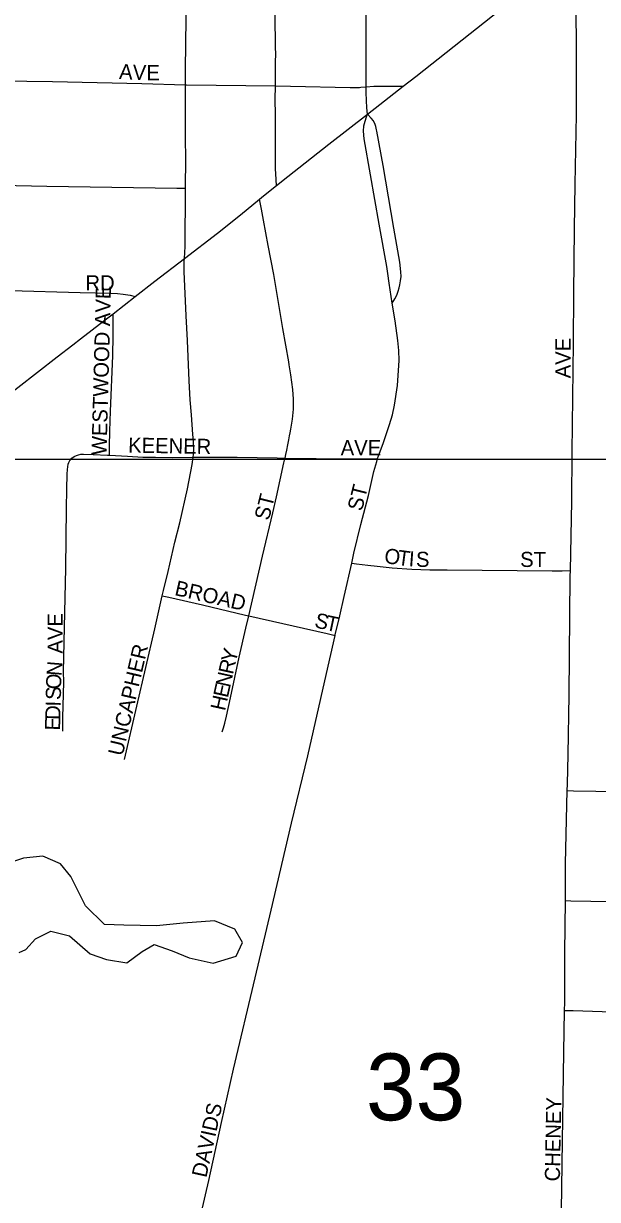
# Model space of a CAD drawing. Extents: x -97 to 34, y -21 to 22.
# Drawn here: x 4.741 to 5.1, y 18.009 to 18.745 of the extents above; entities that cross this region are included whole.
import ezdxf

# ---------------------------------------------------------------- set-up
doc = ezdxf.new("R2010")
doc.units = 0
for name, color, linetype in [('GM_X_City_Street', 7, 'Continuous'), ('GM_X_City_Street_Text', 7, 'Continuous'), ('GM_X_Minor_Lake', 7, 'Continuous'), ('GM_X_Section', 7, 'Continuous'), ('GM_X_Section_Text', 7, 'Continuous'), ('GM_X_State_Route', 7, 'Continuous')]:
    doc.layers.add(name, color=color, linetype=linetype)

msp = doc.modelspace()

# ---------------------------------------------------------------- linework, layer by layer
at = {"layer": 'GM_X_City_Street'}
for points in [[(4.89836, 18.70629), (4.89836, 18.70706), (4.89852, 18.72116), (4.89857, 18.72632), (4.89847, 18.73034), (4.89845, 18.73444), (4.89836, 18.73853), (4.89826, 18.74257), (4.89827, 18.74808), (4.89827, 18.75293), (4.89828, 18.7598), (4.89828, 18.7688), (4.89835, 18.77788), (4.89843, 18.78422), (4.89837, 18.79037), (4.89837, 18.79585)], [(4.95537, 18.70568), (4.95529, 18.71536), (4.95521, 18.72156), (4.95534, 18.734), (4.9552, 18.74025), (4.95529, 18.75266), (4.95567, 18.76511), (4.95578, 18.77134), (4.95571, 18.77508), (4.95562, 18.77982), (4.95561, 18.78606), (4.95563, 18.79544)], [(5.08331, 18.40259), (5.08422, 18.44581), (5.08438, 18.4769), (5.08522, 18.54525), (5.08539, 18.57633), (5.08594, 18.61672), (5.08627, 18.6447), (5.08676, 18.66643), (5.08703, 18.68815), (5.08708, 18.72231), (5.08692, 18.76271), (5.08725, 18.77201), (5.08742, 18.77817), (5.08728, 18.7812), (5.08681, 18.79085)], [(4.842, 18.70708), (4.84198, 18.70754), (4.84194, 18.71215), (4.84199, 18.71682), (4.84258, 18.76443)], [(4.72642, 18.70957), (4.75863, 18.70905), (4.81464, 18.70788), (4.842, 18.70708)], [(4.84203, 18.64224), (4.84223, 18.66089), (4.84208, 18.67334), (4.842, 18.70708)], [(4.842, 18.70708), (4.84257, 18.70706), (4.89836, 18.70629)], [(4.89905, 18.64383), (4.89862, 18.65117), (4.89845, 18.65426), (4.89845, 18.66671), (4.89841, 18.67749), (4.89837, 18.68845), (4.89828, 18.69774), (4.89836, 18.70629)], [(4.89836, 18.70629), (4.90793, 18.70612), (4.94533, 18.70539), (4.94688, 18.70539), (4.94925, 18.70539), (4.95103, 18.70542), (4.95201, 18.70548), (4.95537, 18.70568)], [(4.95621, 18.68865), (4.95576, 18.69255), (4.95557, 18.69714), (4.95534, 18.70217), (4.95537, 18.70568)], [(4.95537, 18.70568), (4.96016, 18.70607), (4.96202, 18.70614), (4.96445, 18.70624), (4.96758, 18.70618), (4.97539, 18.70612), (4.97849, 18.7061)], [(4.97166, 18.57029), (4.96972, 18.58266), (4.96881, 18.58871), (4.96819, 18.59316), (4.96336, 18.61965), (4.95791, 18.65057), (4.95399, 18.67322), (4.95359, 18.67796), (4.9539, 18.68126), (4.95457, 18.6843), (4.9556, 18.68704), (4.95621, 18.68865)], [(4.97166, 18.57029), (4.97324, 18.57287), (4.97446, 18.57526), (4.97527, 18.57763), (4.97597, 18.57974), (4.97641, 18.58168), (4.9769, 18.58409), (4.97729, 18.58682), (4.97711, 18.58992), (4.97642, 18.59591), (4.97255, 18.61713), (4.96589, 18.65641), (4.96202, 18.67787), (4.96186, 18.67878), (4.96159, 18.67991), (4.96137, 18.68083), (4.96092, 18.68214), (4.95985, 18.68438), (4.95843, 18.68611), (4.95621, 18.68865)], [(4.72621, 18.64411), (4.75512, 18.64341), (4.83665, 18.6423), (4.84203, 18.64224)], [(4.84136, 18.59824), (4.84183, 18.60569), (4.84177, 18.60786), (4.84185, 18.61109), (4.84185, 18.61727), (4.842, 18.62985), (4.84197, 18.63603), (4.84203, 18.64224)], [(4.90446, 18.47314), (4.90493, 18.4754), (4.90552, 18.47811), (4.90624, 18.4814), (4.90681, 18.48454), (4.90729, 18.4871), (4.90771, 18.489), (4.90812, 18.49132), (4.90917, 18.49747), (4.90972, 18.50369), (4.90978, 18.50994), (4.90935, 18.51613), (4.90809, 18.52531), (4.9071, 18.53148), (4.90678, 18.53342), (4.90307, 18.55439), (4.89736, 18.5881), (4.89391, 18.60642), (4.89094, 18.62213), (4.88963, 18.62901), (4.88843, 18.63538)], [(4.84679, 18.47368), (4.84701, 18.47534), (4.8472, 18.47887), (4.84711, 18.48168), (4.84702, 18.48384), (4.84657, 18.48789), (4.84571, 18.50022), (4.84492, 18.50959), (4.8444, 18.52149), (4.84338, 18.5468), (4.84255, 18.56233), (4.84116, 18.58999), (4.84125, 18.59644), (4.84136, 18.59824)], [(4.72613, 18.57818), (4.7324, 18.57804), (4.77596, 18.57685), (4.79494, 18.57641), (4.79938, 18.57618), (4.80302, 18.57589), (4.80732, 18.57524), (4.81057, 18.57446)], [(4.96249, 18.4728), (4.9636, 18.47614), (4.96587, 18.48233), (4.97002, 18.4941), (4.97171, 18.50013), (4.97301, 18.50625), (4.97487, 18.5186), (4.97539, 18.52483), (4.97588, 18.5342), (4.97572, 18.54047), (4.97516, 18.54671), (4.97355, 18.55906), (4.97166, 18.57029)], [(4.79443, 18.47496), (4.7945, 18.48055), (4.79463, 18.48999), (4.79508, 18.50261), (4.79645, 18.53726), (4.7966, 18.54983), (4.79663, 18.5561), (4.79666, 18.56358)], [(4.77088, 18.47309), (4.77235, 18.47409), (4.77366, 18.47478), (4.77505, 18.47524), (4.77644, 18.47548), (4.77813, 18.47555), (4.78407, 18.47545), (4.79325, 18.47502), (4.79443, 18.47496)], [(4.79443, 18.47496), (4.80574, 18.4744), (4.81538, 18.47379), (4.82316, 18.47364), (4.83402, 18.47343), (4.84679, 18.47368)], [(4.82749, 18.38689), (4.82822, 18.39023), (4.8311, 18.40208), (4.83545, 18.42039), (4.83842, 18.43258), (4.84325, 18.45379), (4.84619, 18.46908), (4.84679, 18.47368)], [(4.84679, 18.47368), (4.8496, 18.47373), (4.8745, 18.47361), (4.8995, 18.47321), (4.90446, 18.47314)], [(4.76507, 18.30198), (4.76518, 18.31062), (4.76549, 18.32511), (4.76569, 18.33289), (4.76566, 18.33909), (4.76645, 18.37628), (4.76695, 18.40419), (4.7674, 18.44142), (4.76758, 18.45365), (4.76779, 18.46314), (4.76804, 18.46592), (4.76855, 18.46926), (4.76888, 18.47038), (4.76958, 18.47162), (4.77088, 18.47309)], [(4.8817, 18.37433), (4.89035, 18.41161), (4.89676, 18.43888), (4.89903, 18.44892), (4.90368, 18.47023), (4.90433, 18.47264), (4.90446, 18.47314)], [(4.90446, 18.47314), (4.94329, 18.47256), (4.95584, 18.47272), (4.96249, 18.4728)], [(4.94624, 18.40725), (4.94764, 18.41349), (4.95202, 18.43157), (4.95666, 18.44964), (4.96013, 18.46473), (4.9619, 18.47104), (4.96249, 18.4728)], [(4.9358, 18.36197), (4.93587, 18.36227), (4.93885, 18.37423), (4.94157, 18.38631), (4.94624, 18.40725)], [(4.94624, 18.40725), (4.94925, 18.40689), (4.95629, 18.40604), (4.96216, 18.40534), (4.97151, 18.4044), (4.98402, 18.40352), (4.99519, 18.40314), (5.00599, 18.40308), (5.07192, 18.40241), (5.0782, 18.4025), (5.08331, 18.40259)], [(5.08138, 18.26474), (5.08147, 18.26872), (5.08182, 18.28735), (5.08244, 18.32463), (5.08324, 18.39922), (5.08331, 18.40259)], [(4.80378, 18.28433), (4.81153, 18.31764), (4.82288, 18.36607), (4.82749, 18.38689)], [(4.82749, 18.38689), (4.8317, 18.38593), (4.85272, 18.3811), (4.87973, 18.37478), (4.8817, 18.37433)], [(4.86503, 18.30155), (4.86588, 18.30417), (4.86668, 18.3071), (4.86767, 18.3113), (4.87031, 18.32279), (4.8756, 18.34832), (4.87985, 18.36646), (4.8817, 18.37433)], [(4.8817, 18.37433), (4.93082, 18.3631), (4.9358, 18.36197)], [(4.84651, 17.97642), (4.85676, 18.02036), (4.86457, 18.05681), (4.87208, 18.09012), (4.88581, 18.14752), (4.89567, 18.18987), (4.90857, 18.24427), (4.91877, 18.28654), (4.93052, 18.33804), (4.9358, 18.36197)], [(5.08014, 18.19589), (5.08031, 18.219), (5.08138, 18.26474)], [(5.08138, 18.26474), (5.08526, 18.26468), (5.11323, 18.26429), (5.15055, 18.26441), (5.18164, 18.26398), (5.21896, 18.26363), (5.26248, 18.26263), (5.29669, 18.26226), (5.30795, 18.26219), (5.31192, 18.26216)], [(5.0797, 18.12705), (5.07979, 18.13199), (5.07989, 18.16307), (5.08014, 18.19589)], [(5.08014, 18.19589), (5.08367, 18.19579), (5.09613, 18.19548), (5.13016, 18.19507), (5.15536, 18.19473), (5.17721, 18.19458), (5.20843, 18.19448), (5.22716, 18.19443), (5.25211, 18.19399), (5.27146, 18.19375), (5.27676, 18.19362), (5.28022, 18.19353)], [(5.07773, 17.97367), (5.0777, 17.97771), (5.07761, 17.98707), (5.07829, 18.04501), (5.07921, 18.10094), (5.0797, 18.12705)], [(5.0797, 18.12705), (5.08502, 18.12687), (5.10318, 18.12627), (5.12505, 18.12611), (5.14974, 18.12618), (5.1837, 18.12578), (5.22383, 18.12537), (5.24234, 18.12468), (5.24782, 18.12447)]]:
    msp.add_lwpolyline(points, dxfattribs=at)
at = {"layer": 'GM_X_Minor_Lake'}
msp.add_lwpolyline([(4.73773, 18.16329), (4.74192, 18.16511), (4.74808, 18.17183), (4.75761, 18.17659), (4.76928, 18.17374), (4.78233, 18.16252), (4.79248, 18.15893), (4.8053, 18.15681), (4.81486, 18.16385), (4.8225, 18.16827), (4.83377, 18.16428), (4.84429, 18.15993), (4.85936, 18.15664), (4.87379, 18.16094), (4.87771, 18.16959), (4.87294, 18.17801), (4.86017, 18.18316), (4.84048, 18.18161), (4.82382, 18.18), (4.80341, 18.18035), (4.79133, 18.18094), (4.77942, 18.19252), (4.77027, 18.21088), (4.76359, 18.21896), (4.75271, 18.22369), (4.74059, 18.22239), (4.72881, 18.21842)], dxfattribs=at)
at = {"layer": 'GM_X_Section'}
for points in [[(4.59865, 19.47855), (5.59615, 19.47364), (5.59082, 18.47236), (4.59557, 18.47233)], [(4.59557, 18.47233), (5.59082, 18.47236), (5.58508, 17.4654), (4.58268, 17.47301)]]:
    msp.add_lwpolyline(points, close=True, dxfattribs=at)
at = {"layer": 'GM_X_State_Route'}
for points in [[(4.98638, 18.71231), (5.03452, 18.75017), (5.05126, 18.76358), (5.08681, 18.79085), (5.09993, 18.80091), (5.1099, 18.80832), (5.12212, 18.81778), (5.13398, 18.82696)], [(4.95621, 18.68865), (4.96387, 18.6946), (4.97849, 18.7061), (4.98638, 18.71231)], [(4.68492, 18.47676), (4.6901, 18.48075), (4.69624, 18.48537), (4.69926, 18.48771), (4.70245, 18.49013), (4.72685, 18.50939), (4.73704, 18.51744), (4.76154, 18.53663), (4.77134, 18.54416), (4.77628, 18.54774), (4.79093, 18.5591), (4.79666, 18.56358), (4.81057, 18.57446), (4.82282, 18.58404), (4.84136, 18.59824), (4.86214, 18.61412), (4.87657, 18.62549), (4.88843, 18.63538), (4.89094, 18.63748), (4.89905, 18.64383), (4.90624, 18.64947), (4.93198, 18.66984), (4.95621, 18.68865)]]:
    msp.add_lwpolyline(points, dxfattribs=at)

# ---------------------------------------------------------------- texts
at = {"layer": 'GM_X_City_Street_Text'}
for s, height, rotation, p in [('A', 0.00947, 356.71954, (4.80027, 18.71073)), ('V', 0.00947, 357.83103, (4.80879, 18.71024)), ('E', 0.00947, 359.8075, (4.81747, 18.70992)), ('RD', 0.00947, 0.00001, (4.77933, 18.57822)), ('WESTWOOD AVE', 0.0094697, 88.47993, (4.79255, 18.47484)), ('AVE', 0.00947, 90, (5.08338, 18.52311)), ('KEENER', 0.00947, 358.99363, (4.80604, 18.47656)), ('AVE', 0.00947, 0.00001, (4.93933, 18.47489)), ('ST', 0.00947, 75.97339, (4.89427, 18.43355)), ('ST', 0.00947, 75.97339, (4.9526, 18.43938)), ('O', 0.00947, 352.34903, (4.96624, 18.40738)), ('T', 0.00947, 352.41055, (4.97451, 18.40627)), ('I', 0.00947, 355.85457, (4.98174, 18.40533)), ('S', 0.00947, 359.11632, (4.98648, 18.405)), ('ST', 0.00947, 0.00001, (5.05183, 18.40489)), ('BROAD', 0.00947, 347.09521, (4.83473, 18.38735)), ('AVE', 0.00947, 90, (4.76505, 18.35061)), ('S', 0.00947, 345.27452, (4.92232, 18.36733)), ('T', 0.00947, 348.0528, (4.92926, 18.36552)), ('UNCAPHER', 0.00947, 76.89172, (4.80259, 18.28602)), ('Y', 0.00947, 76.04857, (4.8734, 18.34437)), ('N', 0.00947, 85.3398, (4.76426, 18.33634)), ('R', 0.00947, 77.5308, (4.8718, 18.33711)), ('O', 0.00947, 88.51382, (4.76405, 18.32815)), ('N', 0.00947, 77.50675, (4.87, 18.32897)), ('S', 0.00947, 88.52477, (4.76388, 18.32148)), ('E', 0.00947, 77.52475, (4.86856, 18.32246)), ('I', 0.00947, 88.46955, (4.76377, 18.31731)), ('H', 0.00947, 77.50675, (4.86676, 18.31433)), ('D', 0.00947, 88.51382, (4.76355, 18.30898)), ('E', 0.00947, 88.52419, (4.76338, 18.30232)), ('DAVIDS', 0.00947, 77.5944, (4.85508, 18.02181)), ('CHENEY', 0.00947, 88.97752, (5.07671, 18.01981))]:
    msp.add_text(s, height=height, rotation=rotation, dxfattribs=at).set_placement(p)
at = {"layer": 'GM_X_Section_Text'}
msp.add_text('33', height=0.041856, rotation=0.00001, dxfattribs=at).set_placement((4.95516, 18.05818))

doc.saveas('drawing.dxf')
